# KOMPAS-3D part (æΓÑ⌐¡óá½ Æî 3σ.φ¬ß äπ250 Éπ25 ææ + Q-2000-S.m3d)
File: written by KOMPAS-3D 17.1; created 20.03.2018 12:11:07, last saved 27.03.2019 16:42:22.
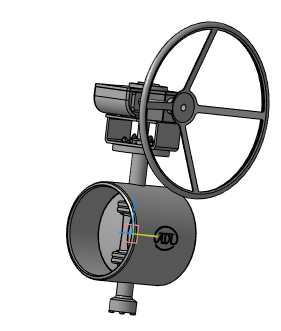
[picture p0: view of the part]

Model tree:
1. Операция без истории:2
